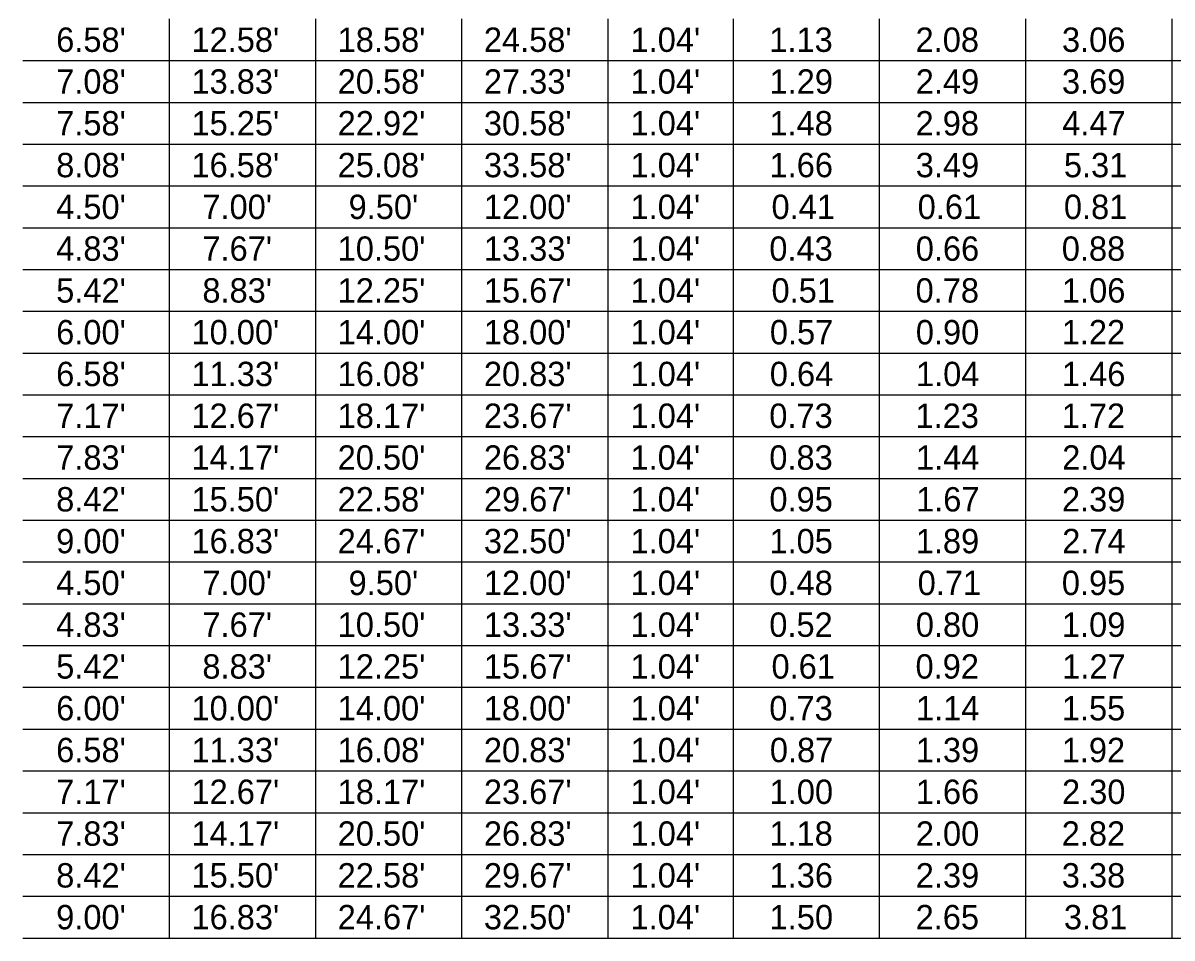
# Model space of a CAD drawing. Extents: x -1.3 to 14.4, y 0 to 7.8.
# Drawn here: x 6.38 to 9.681, y 2.49 to 5.118 of the extents above; entities that cross this region are included whole.
import ezdxf

# ---------------------------------------------------------------- set-up
doc = ezdxf.new("R2010")
doc.units = 0
doc.layers.add('Table', color=7, linetype='Continuous')

msp = doc.modelspace()

# ---------------------------------------------------------------- linework, layer by layer
at = {"layer": 'Table'}
for points in [[(6.8, 5.13), (6.8, 5.01), (6.8, 4.89), (6.8, 4.77), (6.8, 4.65), (6.8, 4.53), (6.8, 4.41), (6.8, 4.29), (6.8, 4.17), (6.8, 4.05), (6.8, 3.93), (6.8, 3.81), (6.8, 3.69), (6.8, 3.57), (6.8, 3.45), (6.8, 3.33), (6.8, 3.21), (6.8, 3.09), (6.8, 2.97), (6.8, 2.85), (6.8, 2.73), (6.8, 2.61), (6.8, 2.49)], [(7.22, 5.13), (7.22, 5.01), (7.22, 4.89), (7.22, 4.77), (7.22, 4.65), (7.22, 4.53), (7.22, 4.41), (7.22, 4.29), (7.22, 4.17), (7.22, 4.05), (7.22, 3.93), (7.22, 3.81), (7.22, 3.69), (7.22, 3.57), (7.22, 3.45), (7.22, 3.33), (7.22, 3.21), (7.22, 3.09), (7.22, 2.97), (7.22, 2.85), (7.22, 2.73), (7.22, 2.61), (7.22, 2.49)], [(7.64, 5.13), (7.64, 5.01), (7.64, 4.89), (7.64, 4.77), (7.64, 4.65), (7.64, 4.53), (7.64, 4.41), (7.64, 4.29), (7.64, 4.17), (7.64, 4.05), (7.64, 3.93), (7.64, 3.81), (7.64, 3.69), (7.64, 3.57), (7.64, 3.45), (7.64, 3.33), (7.64, 3.21), (7.64, 3.09), (7.64, 2.97), (7.64, 2.85), (7.64, 2.73), (7.64, 2.61), (7.64, 2.49)], [(8.06, 5.13), (8.06, 5.01), (8.06, 4.89), (8.06, 4.77), (8.06, 4.65), (8.06, 4.53), (8.06, 4.41), (8.06, 4.29), (8.06, 4.17), (8.06, 4.05), (8.06, 3.93), (8.06, 3.81), (8.06, 3.69), (8.06, 3.57), (8.06, 3.45), (8.06, 3.33), (8.06, 3.21), (8.06, 3.09), (8.06, 2.97), (8.06, 2.85), (8.06, 2.73), (8.06, 2.61), (8.06, 2.49)], [(8.42, 5.13), (8.42, 5.01), (8.42, 4.89), (8.42, 4.77), (8.42, 4.65), (8.42, 4.53), (8.42, 4.41), (8.42, 4.29), (8.42, 4.17), (8.42, 4.05), (8.42, 3.93), (8.42, 3.81), (8.42, 3.69), (8.42, 3.57), (8.42, 3.45), (8.42, 3.33), (8.42, 3.21), (8.42, 3.09), (8.42, 2.97), (8.42, 2.85), (8.42, 2.73), (8.42, 2.61), (8.42, 2.49)], [(8.84, 5.13), (8.84, 5.01), (8.84, 4.89), (8.84, 4.77), (8.84, 4.65), (8.84, 4.53), (8.84, 4.41), (8.84, 4.29), (8.84, 4.17), (8.84, 4.05), (8.84, 3.93), (8.84, 3.81), (8.84, 3.69), (8.84, 3.57), (8.84, 3.45), (8.84, 3.33), (8.84, 3.21), (8.84, 3.09), (8.84, 2.97), (8.84, 2.85), (8.84, 2.73), (8.84, 2.61), (8.84, 2.49)], [(9.26, 5.13), (9.26, 5.01), (9.26, 4.89), (9.26, 4.77), (9.26, 4.65), (9.26, 4.53), (9.26, 4.41), (9.26, 4.29), (9.26, 4.17), (9.26, 4.05), (9.26, 3.93), (9.26, 3.81), (9.26, 3.69), (9.26, 3.57), (9.26, 3.45), (9.26, 3.33), (9.26, 3.21), (9.26, 3.09), (9.26, 2.97), (9.26, 2.85), (9.26, 2.73), (9.26, 2.61), (9.26, 2.49)], [(9.68, 5.13), (9.68, 5.01), (9.68, 4.89), (9.68, 4.77), (9.68, 4.65), (9.68, 4.53), (9.68, 4.41), (9.68, 4.29), (9.68, 4.17), (9.68, 4.05), (9.68, 3.93), (9.68, 3.81), (9.68, 3.69), (9.68, 3.57), (9.68, 3.45), (9.68, 3.33), (9.68, 3.21), (9.68, 3.09), (9.68, 2.97), (9.68, 2.85), (9.68, 2.73), (9.68, 2.61), (9.68, 2.49)], [(6.38, 5.01), (6.8, 5.01), (7.22, 5.01), (7.64, 5.01), (8.06, 5.01), (8.42, 5.01), (8.84, 5.01), (9.26, 5.01), (9.68, 5.01), (10.1, 5.01), (10.52, 5.01), (10.94, 5.01), (11.36, 5.01), (11.78, 5.01), (12.2, 5.01), (12.62, 5.01), (13.04, 5.01), (13.46, 5.01)], [(6.38, 4.89), (6.8, 4.89), (7.22, 4.89), (7.64, 4.89), (8.06, 4.89), (8.42, 4.89), (8.84, 4.89), (9.26, 4.89), (9.68, 4.89), (10.1, 4.89), (10.52, 4.89), (10.94, 4.89), (11.36, 4.89), (11.78, 4.89), (12.2, 4.89), (12.62, 4.89), (13.04, 4.89), (13.46, 4.89)], [(6.38, 4.77), (6.8, 4.77), (7.22, 4.77), (7.64, 4.77), (8.06, 4.77), (8.42, 4.77), (8.84, 4.77), (9.26, 4.77), (9.68, 4.77), (10.1, 4.77), (10.52, 4.77), (10.94, 4.77), (11.36, 4.77), (11.78, 4.77), (12.2, 4.77), (12.62, 4.77), (13.04, 4.77), (13.46, 4.77)], [(6.38, 4.65), (6.8, 4.65), (7.22, 4.65), (7.64, 4.65), (8.06, 4.65), (8.42, 4.65), (8.84, 4.65), (9.26, 4.65), (9.68, 4.65), (10.1, 4.65), (10.52, 4.65), (10.94, 4.65), (11.36, 4.65), (11.78, 4.65), (12.2, 4.65), (12.62, 4.65), (13.04, 4.65), (13.46, 4.65)], [(6.38, 4.53), (6.8, 4.53), (7.22, 4.53), (7.64, 4.53), (8.06, 4.53), (8.42, 4.53), (8.84, 4.53), (9.26, 4.53), (9.68, 4.53), (10.1, 4.53), (10.52, 4.53), (10.94, 4.53), (11.36, 4.53), (11.78, 4.53), (12.2, 4.53), (12.62, 4.53), (13.04, 4.53), (13.46, 4.53)], [(6.38, 4.41), (6.8, 4.41), (7.22, 4.41), (7.64, 4.41), (8.06, 4.41), (8.42, 4.41), (8.84, 4.41), (9.26, 4.41), (9.68, 4.41), (10.1, 4.41), (10.52, 4.41), (10.94, 4.41), (11.36, 4.41), (11.78, 4.41), (12.2, 4.41), (12.62, 4.41), (13.04, 4.41), (13.46, 4.41)], [(6.38, 4.29), (6.8, 4.29), (7.22, 4.29), (7.64, 4.29), (8.06, 4.29), (8.42, 4.29), (8.84, 4.29), (9.26, 4.29), (9.68, 4.29), (10.1, 4.29), (10.52, 4.29), (10.94, 4.29), (11.36, 4.29), (11.78, 4.29), (12.2, 4.29), (12.62, 4.29), (13.04, 4.29), (13.46, 4.29)], [(6.38, 4.17), (6.8, 4.17), (7.22, 4.17), (7.64, 4.17), (8.06, 4.17), (8.42, 4.17), (8.84, 4.17), (9.26, 4.17), (9.68, 4.17), (10.1, 4.17), (10.52, 4.17), (10.94, 4.17), (11.36, 4.17), (11.78, 4.17), (12.2, 4.17), (12.62, 4.17), (13.04, 4.17), (13.46, 4.17)], [(6.38, 4.05), (6.8, 4.05), (7.22, 4.05), (7.64, 4.05), (8.06, 4.05), (8.42, 4.05), (8.84, 4.05), (9.26, 4.05), (9.68, 4.05), (10.1, 4.05), (10.52, 4.05), (10.94, 4.05), (11.36, 4.05), (11.78, 4.05), (12.2, 4.05), (12.62, 4.05), (13.04, 4.05), (13.46, 4.05)], [(6.38, 3.93), (6.8, 3.93), (7.22, 3.93), (7.64, 3.93), (8.06, 3.93), (8.42, 3.93), (8.84, 3.93), (9.26, 3.93), (9.68, 3.93), (10.1, 3.93), (10.52, 3.93), (10.94, 3.93), (11.36, 3.93), (11.78, 3.93), (12.2, 3.93), (12.62, 3.93), (13.04, 3.93), (13.46, 3.93)], [(6.38, 3.81), (6.8, 3.81), (7.22, 3.81), (7.64, 3.81), (8.06, 3.81), (8.42, 3.81), (8.84, 3.81), (9.26, 3.81), (9.68, 3.81), (10.1, 3.81), (10.52, 3.81), (10.94, 3.81), (11.36, 3.81), (11.78, 3.81), (12.2, 3.81), (12.62, 3.81), (13.04, 3.81), (13.46, 3.81)], [(6.38, 3.69), (6.8, 3.69), (7.22, 3.69), (7.64, 3.69), (8.06, 3.69), (8.42, 3.69), (8.84, 3.69), (9.26, 3.69), (9.68, 3.69), (10.1, 3.69), (10.52, 3.69), (10.94, 3.69), (11.36, 3.69), (11.78, 3.69), (12.2, 3.69), (12.62, 3.69), (13.04, 3.69), (13.46, 3.69)], [(6.38, 3.57), (6.8, 3.57), (7.22, 3.57), (7.64, 3.57), (8.06, 3.57), (8.42, 3.57), (8.84, 3.57), (9.26, 3.57), (9.68, 3.57), (10.1, 3.57), (10.52, 3.57), (10.94, 3.57), (11.36, 3.57), (11.78, 3.57), (12.2, 3.57), (12.62, 3.57), (13.04, 3.57), (13.46, 3.57)], [(6.38, 3.45), (6.8, 3.45), (7.22, 3.45), (7.64, 3.45), (8.06, 3.45), (8.42, 3.45), (8.84, 3.45), (9.26, 3.45), (9.68, 3.45), (10.1, 3.45), (10.52, 3.45), (10.94, 3.45), (11.36, 3.45), (11.78, 3.45), (12.2, 3.45), (12.62, 3.45), (13.04, 3.45), (13.46, 3.45)], [(6.38, 3.33), (6.8, 3.33), (7.22, 3.33), (7.64, 3.33), (8.06, 3.33), (8.42, 3.33), (8.84, 3.33), (9.26, 3.33), (9.68, 3.33), (10.1, 3.33), (10.52, 3.33), (10.94, 3.33), (11.36, 3.33), (11.78, 3.33), (12.2, 3.33), (12.62, 3.33), (13.04, 3.33), (13.46, 3.33)], [(6.38, 3.21), (6.8, 3.21), (7.22, 3.21), (7.64, 3.21), (8.06, 3.21), (8.42, 3.21), (8.84, 3.21), (9.26, 3.21), (9.68, 3.21), (10.1, 3.21), (10.52, 3.21), (10.94, 3.21), (11.36, 3.21), (11.78, 3.21), (12.2, 3.21), (12.62, 3.21), (13.04, 3.21), (13.46, 3.21)], [(6.38, 3.09), (6.8, 3.09), (7.22, 3.09), (7.64, 3.09), (8.06, 3.09), (8.42, 3.09), (8.84, 3.09), (9.26, 3.09), (9.68, 3.09), (10.1, 3.09), (10.52, 3.09), (10.94, 3.09), (11.36, 3.09), (11.78, 3.09), (12.2, 3.09), (12.62, 3.09), (13.04, 3.09), (13.46, 3.09)], [(6.38, 2.97), (6.8, 2.97), (7.22, 2.97), (7.64, 2.97), (8.06, 2.97), (8.42, 2.97), (8.84, 2.97), (9.26, 2.97), (9.68, 2.97), (10.1, 2.97), (10.52, 2.97), (10.94, 2.97), (11.36, 2.97), (11.78, 2.97), (12.2, 2.97), (12.62, 2.97), (13.04, 2.97), (13.46, 2.97)], [(6.38, 2.85), (6.8, 2.85), (7.22, 2.85), (7.64, 2.85), (8.06, 2.85), (8.42, 2.85), (8.84, 2.85), (9.26, 2.85), (9.68, 2.85), (10.1, 2.85), (10.52, 2.85), (10.94, 2.85), (11.36, 2.85), (11.78, 2.85), (12.2, 2.85), (12.62, 2.85), (13.04, 2.85), (13.46, 2.85)], [(6.38, 2.73), (6.8, 2.73), (7.22, 2.73), (7.64, 2.73), (8.06, 2.73), (8.42, 2.73), (8.84, 2.73), (9.26, 2.73), (9.68, 2.73), (10.1, 2.73), (10.52, 2.73), (10.94, 2.73), (11.36, 2.73), (11.78, 2.73), (12.2, 2.73), (12.62, 2.73), (13.04, 2.73), (13.46, 2.73)], [(6.38, 2.61), (6.8, 2.61), (7.22, 2.61), (7.64, 2.61), (8.06, 2.61), (8.42, 2.61), (8.84, 2.61), (9.26, 2.61), (9.68, 2.61), (10.1, 2.61), (10.52, 2.61), (10.94, 2.61), (11.36, 2.61), (11.78, 2.61), (12.2, 2.61), (12.62, 2.61), (13.04, 2.61), (13.46, 2.61)], [(6.38, 2.49), (6.8, 2.49), (7.22, 2.49), (7.64, 2.49), (8.06, 2.49), (8.42, 2.49), (8.84, 2.49), (9.26, 2.49), (9.68, 2.49), (10.1, 2.49), (10.52, 2.49), (10.94, 2.49), (11.36, 2.49), (11.78, 2.49), (12.2, 2.49), (12.62, 2.49), (13.04, 2.49), (13.46, 2.49)]]:
    msp.add_lwpolyline(points, dxfattribs=at)

# ---------------------------------------------------------------- texts
for s, p in [("6.58'", (6.4754, 5.035)), ("12.58'", (6.864, 5.035)), ("18.58'", (7.284, 5.035)), ("24.58'", (7.704, 5.035)), ("1.04'", (8.1254, 5.035)), ('1.13', (8.524, 5.035)), ('2.08', (8.9442, 5.035)), ('3.06', (9.3647, 5.035)), ("7.08'", (6.4754, 4.915)), ("13.83'", (6.864, 4.915)), ("20.58'", (7.284, 4.915)), ("27.33'", (7.704, 4.915)), ("1.04'", (8.1254, 4.915)), ('1.29', (8.5247, 4.915)), ('2.49', (8.9447, 4.915)), ('3.69', (9.3647, 4.915)), ("7.58'", (6.4754, 4.795)), ("15.25'", (6.864, 4.795)), ("22.92'", (7.284, 4.795)), ("30.58'", (7.704, 4.795)), ("1.04'", (8.1254, 4.795)), ('1.48', (8.5242, 4.795)), ('2.98', (8.9442, 4.795)), ('4.47', (9.3656, 4.795)), ("8.08'", (6.4754, 4.675)), ("16.58'", (6.864, 4.675)), ("25.08'", (7.284, 4.675)), ("33.58'", (7.704, 4.675)), ("1.04'", (8.1254, 4.675)), ('1.66', (8.5247, 4.675)), ('3.49', (8.9447, 4.675)), ('5.31', (9.3703, 4.675)), ("4.50'", (6.4754, 4.555)), ("7.00'", (6.8954, 4.555)), ("9.50'", (7.3154, 4.555)), ("12.00'", (7.704, 4.555)), ("1.04'", (8.1254, 4.555)), ('0.61', (8.9503, 4.555)), ("4.83'", (6.4754, 4.435)), ("7.67'", (6.8954, 4.435)), ("10.50'", (7.284, 4.435)), ("13.33'", (7.704, 4.435)), ("1.04'", (8.1254, 4.435)), ("5.42'", (6.4754, 4.315)), ("8.83'", (6.8954, 4.315)), ("12.25'", (7.284, 4.315)), ("15.67'", (7.704, 4.315)), ("1.04'", (8.1254, 4.315)), ('0.51', (8.5303, 4.315)), ("6.00'", (6.4754, 4.195)), ("10.00'", (6.864, 4.195)), ("14.00'", (7.284, 4.195)), ("18.00'", (7.704, 4.195)), ("1.04'", (8.1254, 4.195)), ('0.90', (8.9449, 4.195)), ("6.58'", (6.4754, 4.075)), ("11.33'", (6.864, 4.075)), ("16.08'", (7.284, 4.075)), ("20.83'", (7.704, 4.075)), ("1.04'", (8.1254, 4.075)), ("7.17'", (6.4754, 3.955)), ("12.67'", (6.864, 3.955)), ("18.17'", (7.284, 3.955)), ("23.67'", (7.704, 3.955)), ("1.04'", (8.1254, 3.955)), ('0.73', (8.524, 3.955)), ('1.23', (8.944, 3.955)), ('1.72', (9.364, 3.955)), ("7.83'", (6.4754, 3.835)), ("14.17'", (6.864, 3.835)), ("20.50'", (7.284, 3.835)), ("26.83'", (7.704, 3.835)), ("1.04'", (8.1254, 3.835)), ('0.83', (8.524, 3.835)), ('1.44', (8.9454, 3.835)), ('2.04', (9.3654, 3.835)), ("8.42'", (6.4754, 3.715)), ("15.50'", (6.864, 3.715)), ("22.58'", (7.284, 3.715)), ("29.67'", (7.704, 3.715)), ("1.04'", (8.1254, 3.715)), ('0.95', (8.5243, 3.715)), ('1.67', (8.9456, 3.715)), ('2.39', (9.3647, 3.715)), ("9.00'", (6.4754, 3.595)), ("16.83'", (6.864, 3.595)), ("24.67'", (7.284, 3.595)), ("32.50'", (7.704, 3.595)), ("1.04'", (8.1254, 3.595)), ('1.05', (8.5243, 3.595)), ('1.89', (8.9447, 3.595)), ('2.74', (9.3654, 3.595)), ("4.50'", (6.4754, 3.475)), ("7.00'", (6.8954, 3.475)), ("9.50'", (7.3154, 3.475)), ("12.00'", (7.704, 3.475)), ("1.04'", (8.1254, 3.475)), ('0.48', (8.5242, 3.475)), ('0.71', (8.9503, 3.475)), ('0.95', (9.3643, 3.475)), ("4.83'", (6.4754, 3.355)), ("7.67'", (6.8954, 3.355)), ("10.50'", (7.284, 3.355)), ("13.33'", (7.704, 3.355)), ("1.04'", (8.1254, 3.355)), ('0.52', (8.524, 3.355)), ('0.80', (8.9449, 3.355)), ('1.09', (9.3647, 3.355)), ("5.42'", (6.4754, 3.235)), ("8.83'", (6.8954, 3.235)), ("12.25'", (7.284, 3.235)), ("15.67'", (7.704, 3.235)), ("1.04'", (8.1254, 3.235)), ('0.61', (8.5303, 3.235)), ('0.92', (8.944, 3.235)), ('1.27', (9.3656, 3.235)), ("6.00'", (6.4754, 3.115)), ("10.00'", (6.864, 3.115)), ("14.00'", (7.284, 3.115)), ("18.00'", (7.704, 3.115)), ("1.04'", (8.1254, 3.115)), ('0.73', (8.524, 3.115)), ('1.14', (8.9454, 3.115)), ('1.55', (9.3643, 3.115)), ("6.58'", (6.4754, 2.995)), ("11.33'", (6.864, 2.995)), ("16.08'", (7.284, 2.995)), ("20.83'", (7.704, 2.995)), ("1.04'", (8.1254, 2.995)), ('0.87', (8.5256, 2.995)), ('1.39', (8.9447, 2.995)), ('1.92', (9.364, 2.995)), ("7.17'", (6.4754, 2.875)), ("12.67'", (6.864, 2.875)), ("18.17'", (7.284, 2.875)), ("23.67'", (7.704, 2.875)), ("1.04'", (8.1254, 2.875)), ('1.00', (8.5249, 2.875)), ('1.66', (8.9447, 2.875)), ('2.30', (9.3649, 2.875)), ("7.83'", (6.4754, 2.755)), ("14.17'", (6.864, 2.755)), ("20.50'", (7.284, 2.755)), ("26.83'", (7.704, 2.755)), ("1.04'", (8.1254, 2.755)), ('1.18', (8.5242, 2.755)), ('2.00', (8.9449, 2.755)), ('2.82', (9.364, 2.755)), ("8.42'", (6.4754, 2.635)), ("15.50'", (6.864, 2.635)), ("22.58'", (7.284, 2.635)), ("29.67'", (7.704, 2.635)), ("1.04'", (8.1254, 2.635)), ('1.36', (8.5247, 2.635)), ('2.39', (8.9447, 2.635)), ('3.38', (9.3642, 2.635)), ("9.00'", (6.4754, 2.515)), ("16.83'", (6.864, 2.515)), ("24.67'", (7.284, 2.515)), ("32.50'", (7.704, 2.515)), ("1.04'", (8.1254, 2.515)), ('1.50', (8.5249, 2.515)), ('2.65', (8.9443, 2.515)), ('3.81', (9.3703, 2.515))]:
    msp.add_text(s, height=0.07, rotation=0, dxfattribs=at).set_placement(p)
for s, p in [('0.41', (8.5303, 4.555)), ('0.81', (9.3703, 4.555)), ('0.43', (8.524, 4.435)), ('0.66', (8.9447, 4.435)), ('0.88', (9.3642, 4.435)), ('0.78', (8.9442, 4.315)), ('1.06', (9.3647, 4.315)), ('0.57', (8.5256, 4.195)), ('1.22', (9.364, 4.195)), ('0.64', (8.5254, 4.075)), ('1.04', (8.9454, 4.075)), ('1.46', (9.3647, 4.075))]:
    msp.add_text(s, height=0.07, dxfattribs=at).set_placement(p)

doc.saveas('drawing.dxf')
